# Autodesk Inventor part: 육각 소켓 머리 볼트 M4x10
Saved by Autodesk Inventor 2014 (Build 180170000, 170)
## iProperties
Created: 2024-11
Part Number: 육각 소켓 머리 볼트 M4x10
Material: 일반
Document SubType Name: Modeling
Designer: dg
Density: 1 g/cm^3
Appearance: 기본값
Author: dg
Author: jhkim
Description: 6각머리 태핑 나사
Creation Date: 2024-10-25
Sending System: Autodesk Inventor 2025
Preprocessor: ST-DEVELOPER v20
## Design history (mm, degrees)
node "육각 소켓 머리 볼트 M4x101"
body "Solid1"
node "기준1"
